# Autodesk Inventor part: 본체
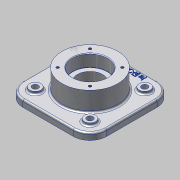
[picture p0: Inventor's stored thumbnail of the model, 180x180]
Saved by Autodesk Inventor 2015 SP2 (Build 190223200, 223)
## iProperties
Created: 2015-07
Part Number: 본체
Material: 알루미늄 6061
Document SubType Name: Modeling
Designer: AMC
Density: 2.7 g/cm^3
Appearance: 알루미늄 - 평지
Mass: 1458.87 g
Surface Area: 802.047 cm^2
Volume: 540.321 cm^3
Author: AMC
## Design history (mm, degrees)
sketch "스케치1"
  geometry: L1 (-75, 75)-(75, 75); L2 (75, 75)-(75, -75); L3 (75, -75)-(-75, -75); L4 (-75, -75)-(-75, 75); L5 (-75, 75)-(75, -75); L6 (75, 75)-(-75, -75); 1 further point
  constraints: 12 end point, 2 midpoint, 2 parallel, 1 horizontal, 1 perpendicular
  dimensions: "d0" = 150 distance of L2.end L3.end; "d1" = 150 distance of L1.end L2.end
extrude "돌출1" new body sketch "스케치1" distance "d2" = 12; taper "d3" = 0 deg
sketch "스케치2"
  geometry: L1 (-49, 49)-(49, -49); L2 (49, 49)-(-49, -49); C1 r 10 at (-49, 49); C2 r 10 at (49, 49); C3 r 10 at (49, -49); C4 r 10 at (-49, -49); 1 further point
  constraints: 4 centre point, 4 coincident, 4 end point, 2 midpoint
  dimensions: "d4" = 98 distance of L1.end L2.end; "d5" = 98 distance of L2.start L1.end; "d6" = 20 diameter of C1; "d7" = 20 diameter of C2; "d8" = 20 diameter of C3; "d9" = 20 diameter of C4
extrude "돌출2" join sketch "스케치2" distance "d11" = 5; taper "d12" = 0 deg
sketch "스케치3"
  geometry: C1 r 50 at (0, 0); 1 further point
  constraints: 1 centre point, 1 coincident
  dimensions: "d13" = 100 diameter of C1
extrude "돌출3" join sketch "스케치3" distance "d14" = 35; taper "d15" = 0 deg
sketch "스케치4"
  geometry: C1 r 50 at (0, 0); 1 further point
  constraints: 1 centre point, 1 coincident
  dimensions: "d16" = 100 diameter of C1
extrude "돌출4" join sketch "스케치4" distance "d17" = 23; taper "d18" = 0 deg
hole "구멍1" diameter "d21" = 11; stored, may be unused: countersink angle "d25" = 90 deg, drill point angle "d27" = 118 deg; dims "d19" = 10, "d20" = 10, "d22" = 6, "d23" = 4, "d24" = 2, "d26" = 8
hole "구멍2" diameter "d30" = 11; stored, may be unused: countersink angle "d34" = 90 deg, drill point angle "d36" = 118 deg; dims "d28" = 10, "d29" = 10, "d31" = 6, "d32" = 4, "d33" = 2, "d35" = 8
hole "구멍3" diameter "d39" = 11; stored, may be unused: countersink angle "d43" = 90 deg, drill point angle "d45" = 118 deg; dims "d37" = 10, "d38" = 10, "d40" = 6, "d41" = 4, "d42" = 2, "d44" = 8
hole "구멍4" diameter "d48" = 11; stored, may be unused: countersink angle "d52" = 90 deg, drill point angle "d54" = 118 deg; dims "d46" = 10, "d47" = 10, "d49" = 6, "d50" = 4, "d51" = 2, "d53" = 8
hole "구멍5" diameter "d57" = 45; stored, may be unused: countersink angle "d61" = 90 deg, drill point angle "d63" = 118 deg; dims "d55" = 10, "d56" = 10, "d58" = 6, "d59" = 62, "d60" = 22, "d62" = 50
hole "구멍6" diameter "d66" = 45; stored, may be unused: countersink angle "d70" = 90 deg, drill point angle "d72" = 0 deg; dims "d64" = 10, "d65" = 10, "d67" = 6, "d68" = 62, "d69" = 22, "d71" = 50
sketch "스케치5"
  geometry: 2 further points
sketch "스케치6"
  geometry: 2 further points
hole "구멍8" sketch "스케치6" at (28.991, 28.991) diameter "d84" = 4.917; stored, may be unused: countersink angle "d88" = 90 deg, drill point angle "d90" = 118 deg; dims "d85" = 10, "d86" = 62, "d87" = 22, "d89" = 13
chamfer "모따기1" distance "d97" = 0.3; stored, may be unused: second distance "d98" = 2, angle "d99" = 45 deg
chamfer "모따기2" distance "d100" = 0.3; stored, may be unused: second distance "d101" = 2, angle "d102" = 45 deg
sketch "스케치7"
  geometry: 2 further points
  constraints: 1 other
feature "엠보싱1" sketch "스케치7" dims "d0" = 150, "d1" = 150, "d104" = 1, "d105" = 0
chamfer "모따기3" distance "d106" = 1; stored, may be unused: second distance "d107" = 2, angle "d108" = 45 deg
chamfer "모따기4" distance "d109" = 1; stored, may be unused: second distance "d110" = 2, angle "d111" = 45 deg
fillet "모깎기1" dims "d112" = 30
fillet "모깎기2" dims "d113" = 3
hole "구멍9" sketch "스케치5" diameter "d114" = 4.917; stored, may be unused: countersink angle "d118" = 90 deg, drill point angle "d120" = 118 deg; dims "d115" = 10, "d116" = 4, "d117" = 2, "d119" = 13
node "솔리드1"
pattern_circular "원형 패턴1" dims angle "d92" = 360 deg
pattern_circular "원형 패턴3" dims angle "d122" = 360 deg
